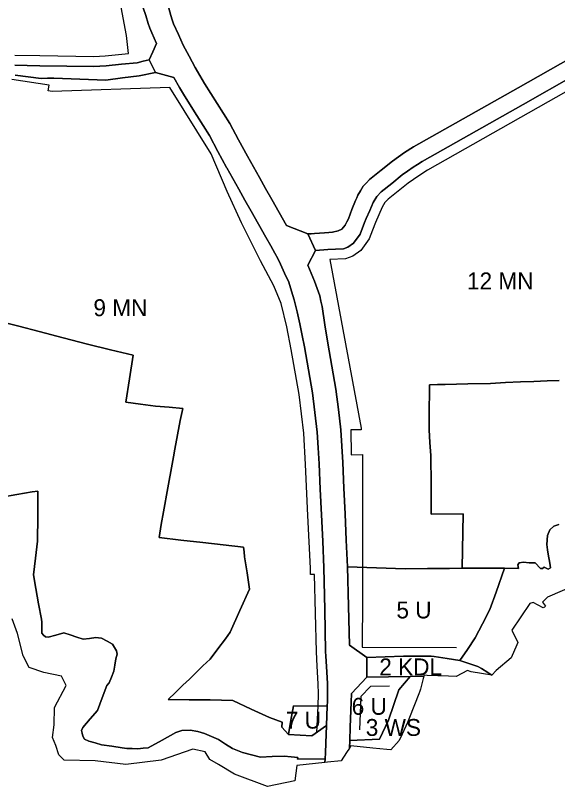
# Model space of a CAD drawing. Extents: x 7423432 to 7425824, y 5537848 to 5539677.
# Drawn here: x 7424289.1 to 7424610, y 5537848 to 5538304.6 of the extents above; entities that cross this region are included whole.
import ezdxf

# ---------------------------------------------------------------- set-up
doc = ezdxf.new("R2010")
doc.units = 0
for name, color, linetype in [('linie_rozgraniczajace', 7, 'Continuous'), ('linie_zabudowy_nieprzekraczalne', 7, 'Continuous'), ('oznaczenia_przeznaczen', 7, 'Continuous')]:
    doc.layers.add(name, color=color, linetype=linetype)

msp = doc.modelspace()

# ---------------------------------------------------------------- linework, layer by layer
at = {"layer": 'linie_rozgraniczajace'}
for points in [[(7424364.77, 5538309.08), (7424366.24, 5538304.49), (7424367.7, 5538299.89), (7424368.77, 5538297.09), (7424369.84, 5538294.29), (7424371.28, 5538291.11), (7424372.71, 5538287.94), (7424370.46, 5538283.14), (7424368.2, 5538278.34), (7424364.67, 5538277.48), (7424361.13, 5538276.62), (7424351.94, 5538275.67), (7424342.76, 5538274.72), (7424339.16, 5538274.52), (7424335.56, 5538274.33), (7424319.54, 5538274.56), (7424303.52, 5538274.8), (7424296.11, 5538274.99), (7424288.7, 5538275.17)], [(7424446.09, 5538157.4), (7424444.38, 5538160.62), (7424442.67, 5538163.84), (7424441.47, 5538166.01), (7424440.28, 5538168.18), (7424437.36, 5538173.35), (7424433, 5538181.05), (7424428.64, 5538188.75), (7424424.99, 5538195.23), (7424421.33, 5538201.71), (7424417.76, 5538208.04), (7424414.19, 5538214.37), (7424413.99, 5538214.5), (7424408.95, 5538224.05), (7424403.91, 5538233.61), (7424396.53, 5538245.3), (7424389.14, 5538257), (7424386.23, 5538262), (7424382.8, 5538267.96), (7424372.08, 5538270.76), (7424368.2, 5538278.34), (7424370.46, 5538283.14), (7424372.71, 5538287.94), (7424371.28, 5538291.11), (7424369.84, 5538294.29), (7424368.77, 5538297.09), (7424367.7, 5538299.89), (7424366.24, 5538304.49), (7424364.77, 5538309.08)], [(7424429.96, 5538214.91), (7424426.39, 5538221.24), (7424421.21, 5538230.93), (7424416.03, 5538240.62), (7424408.57, 5538252.44), (7424401.11, 5538264.26), (7424398.33, 5538269.04), (7424395.55, 5538273.82), (7424392, 5538280.45), (7424388.46, 5538287.09), (7424385.62, 5538293.38), (7424382.77, 5538299.67), (7424381.95, 5538302.08), (7424381.13, 5538304.5), (7424379.86, 5538308.99)], [(7424379.86, 5538308.99), (7424381.13, 5538304.5), (7424381.95, 5538302.08), (7424382.77, 5538299.67), (7424385.62, 5538293.38), (7424388.46, 5538287.09), (7424392, 5538280.45), (7424395.55, 5538273.82), (7424398.33, 5538269.04), (7424401.11, 5538264.26), (7424408.57, 5538252.44), (7424416.03, 5538240.62), (7424421.21, 5538230.93), (7424426.39, 5538221.24), (7424429.96, 5538214.91), (7424433.52, 5538208.59), (7424437.18, 5538202.11), (7424440.83, 5538195.64), (7424445.17, 5538187.97), (7424449.5, 5538180.31), (7424462.18, 5538175.24), (7424466.64, 5538165.51), (7424462.17, 5538156.69), (7424464.16, 5538151.96), (7424466.15, 5538147.23), (7424467.74, 5538142.96), (7424469.34, 5538138.68), (7424469.98, 5538135.45), (7424470.62, 5538132.22), (7424472.32, 5538121.43), (7424474.02, 5538110.65), (7424476.39, 5538096.98), (7424478.76, 5538083.32), (7424480.26, 5538071.27), (7424481.76, 5538059.21), (7424482.32, 5538049.57), (7424482.87, 5538039.92), (7424483.56, 5538024.76), (7424484.24, 5538009.59), (7424484.97, 5537993.86), (7424485.7, 5537978.12), (7424486.31, 5537954.94), (7424486.92, 5537931.75), (7424497.08, 5537924.38), (7424497.11, 5537912.86), (7424488.06, 5537903.12), (7424487.86, 5537898.1), (7424487.67, 5537893.08), (7424487.29, 5537883.18), (7424486.98, 5537875.31), (7424486.86, 5537870.87), (7424485.04, 5537868.13), (7424481.86, 5537863.34), (7424473.91, 5537862.5), (7424472.28, 5537862.33), (7424472.4, 5537864.54), (7424472.6, 5537868.02), (7424472.91, 5537873.7), (7424473.31, 5537884.12), (7424473.72, 5537895.66), (7424473.78, 5537898.35), (7424473.87, 5537903.07), (7424473.83, 5537906.11), (7424473.78, 5537909.14), (7424473.39, 5537915.75), (7424473, 5537922.36), (7424472.83, 5537925.23), (7424472.66, 5537928.1), (7424472.19, 5537952.86), (7424471.71, 5537977.61), (7424470.99, 5537993.28), (7424470.26, 5538008.95), (7424469.57, 5538024.08), (7424468.89, 5538039.2), (7424468.35, 5538048.57), (7424467.81, 5538057.94), (7424466.36, 5538069.6), (7424464.91, 5538081.26), (7424462.56, 5538094.81), (7424460.21, 5538108.36), (7424458.87, 5538115.15), (7424457.53, 5538121.93), (7424455.82, 5538129.08), (7424454.11, 5538136.22), (7424452.48, 5538141.45), (7424450.85, 5538146.69), (7424448.47, 5538152.04), (7424446.09, 5538157.4)], [(7424648.72, 5538296.91), (7424586.75, 5538261.84), (7424524.77, 5538226.77), (7424519.38, 5538223.37), (7424512.31, 5538218.35), (7424505.54, 5538212.92), (7424498.78, 5538207.49), (7424496.89, 5538205.46), (7424495.01, 5538203.43), (7424493.44, 5538200.82), (7424491.86, 5538198.2), (7424491.14, 5538196.63), (7424490.41, 5538195.05), (7424488.31, 5538189.65), (7424486.21, 5538184.24), (7424485.25, 5538182.34), (7424484.29, 5538180.43), (7424482.41, 5538177.97), (7424480.24, 5538176.99), (7424476.88, 5538176.25), (7424474.6, 5538176.07), (7424472.11, 5538175.87), (7424469.16, 5538175.7), (7424466.22, 5538175.53), (7424464.2, 5538175.39), (7424462.18, 5538175.24), (7424449.5, 5538180.31), (7424445.17, 5538187.97), (7424440.83, 5538195.64), (7424437.18, 5538202.11), (7424433.52, 5538208.59), (7424429.96, 5538214.91)], [(7424462.18, 5538175.24), (7424464.2, 5538175.39), (7424466.22, 5538175.53), (7424469.16, 5538175.7), (7424472.11, 5538175.87), (7424474.6, 5538176.07), (7424476.88, 5538176.25), (7424480.24, 5538176.99), (7424482.41, 5538177.97), (7424484.29, 5538180.43), (7424485.25, 5538182.34), (7424486.21, 5538184.24), (7424488.31, 5538189.65), (7424490.41, 5538195.05), (7424491.14, 5538196.63), (7424491.86, 5538198.2), (7424493.44, 5538200.82), (7424495.01, 5538203.43), (7424496.89, 5538205.46), (7424498.78, 5538207.49), (7424505.54, 5538212.92), (7424512.31, 5538218.35), (7424519.38, 5538223.37), (7424524.77, 5538226.77), (7424586.75, 5538261.84), (7424648.72, 5538296.91)], [(7424610.91, 5538088.47), (7424603.87, 5538088.22), (7424595.97, 5538087.93), (7424588.08, 5538087.65), (7424579.16, 5538087.21), (7424570.25, 5538086.76), (7424556.9, 5538086.45), (7424543.55, 5538086.13), (7424538.86, 5538086.02), (7424534.17, 5538085.91), (7424534.14, 5538082.08), (7424534.04, 5538070.65), (7424533.95, 5538059.21), (7424534.46, 5538051.68), (7424534.97, 5538044.15), (7424535.12, 5538026.7), (7424535.28, 5538009.25), (7424554.19, 5538009.46), (7424553.63, 5537977.3), (7424546.07, 5537977.24), (7424532.96, 5537977.14), (7424519.85, 5537977.03), (7424502.78, 5537977.58), (7424485.7, 5537978.12), (7424484.97, 5537993.86), (7424484.24, 5538009.59), (7424483.56, 5538024.76), (7424482.87, 5538039.92), (7424482.32, 5538049.57), (7424481.76, 5538059.21), (7424480.26, 5538071.27), (7424478.76, 5538083.32), (7424476.39, 5538096.98), (7424474.02, 5538110.65), (7424472.32, 5538121.43), (7424470.62, 5538132.22), (7424469.98, 5538135.45), (7424469.34, 5538138.68), (7424467.74, 5538142.96), (7424466.15, 5538147.23), (7424464.16, 5538151.96), (7424462.17, 5538156.69), (7424466.64, 5538165.51), (7424473.97, 5538166.02), (7424478.66, 5538166.22), (7424483.34, 5538166.42), (7424485.94, 5538167.34), (7424489.17, 5538169.73), (7424493.13, 5538175.17), (7424495.77, 5538182), (7424496.71, 5538184.38), (7424498.8, 5538189.1), (7424500.9, 5538193.82), (7424503.04, 5538197.39), (7424505.68, 5538200.22), (7424511.86, 5538205.2), (7424518.04, 5538210.18), (7424521.26, 5538212.43), (7424524.48, 5538214.68), (7424527.15, 5538216.41), (7424529.82, 5538218.13), (7424589.55, 5538251.94), (7424649.28, 5538285.74)], [(7424649.28, 5538285.74), (7424589.55, 5538251.94), (7424529.82, 5538218.13), (7424527.15, 5538216.41), (7424524.48, 5538214.68), (7424521.26, 5538212.43), (7424518.04, 5538210.18), (7424511.86, 5538205.2), (7424505.68, 5538200.22), (7424503.04, 5538197.39), (7424500.9, 5538193.82), (7424498.8, 5538189.1), (7424496.71, 5538184.38), (7424495.77, 5538182), (7424493.13, 5538175.17), (7424489.17, 5538169.73), (7424485.94, 5538167.34), (7424483.34, 5538166.42), (7424478.66, 5538166.22), (7424473.97, 5538166.02), (7424466.64, 5538165.51), (7424462.18, 5538175.24)], [(7424288.7, 5538275.17), (7424296.11, 5538274.99), (7424303.52, 5538274.8), (7424319.54, 5538274.56), (7424335.56, 5538274.33), (7424339.16, 5538274.52), (7424342.76, 5538274.72), (7424351.94, 5538275.67), (7424361.13, 5538276.62), (7424364.67, 5538277.48), (7424368.2, 5538278.34), (7424372.08, 5538270.76), (7424362.33, 5538268.82), (7424352.48, 5538267.59), (7424342.63, 5538266.37), (7424327.25, 5538266.91), (7424311.88, 5538267.45), (7424308.1, 5538267.39), (7424304.32, 5538267.33), (7424296.63, 5538268.28), (7424288.93, 5538269.22)], [(7424288.93, 5538269.22), (7424296.63, 5538268.28), (7424304.32, 5538267.33), (7424308.1, 5538267.39), (7424311.88, 5538267.45), (7424327.25, 5538266.91), (7424342.63, 5538266.37), (7424352.48, 5538267.59), (7424362.33, 5538268.82), (7424372.08, 5538270.76), (7424382.8, 5538267.96), (7424386.23, 5538262), (7424389.14, 5538257), (7424396.53, 5538245.3), (7424403.91, 5538233.61), (7424408.95, 5538224.05), (7424413.99, 5538214.5), (7424414.19, 5538214.37), (7424417.76, 5538208.04), (7424421.33, 5538201.71), (7424424.99, 5538195.23), (7424428.64, 5538188.75), (7424433, 5538181.05), (7424437.36, 5538173.35), (7424440.28, 5538168.18), (7424441.47, 5538166.01), (7424442.67, 5538163.84), (7424444.38, 5538160.62), (7424446.09, 5538157.4), (7424448.47, 5538152.04), (7424450.85, 5538146.69), (7424452.48, 5538141.45), (7424454.11, 5538136.22), (7424455.82, 5538129.08), (7424457.53, 5538121.93), (7424458.87, 5538115.15), (7424460.21, 5538108.36), (7424462.56, 5538094.81), (7424464.91, 5538081.26), (7424466.36, 5538069.6), (7424467.81, 5538057.94), (7424468.35, 5538048.57), (7424468.89, 5538039.2), (7424469.57, 5538024.08), (7424470.26, 5538008.95), (7424470.99, 5537993.28), (7424471.71, 5537977.61), (7424472.19, 5537952.86), (7424472.66, 5537928.1), (7424472.83, 5537925.23), (7424473, 5537922.36), (7424473.39, 5537915.75), (7424473.78, 5537909.14), (7424473.83, 5537906.11), (7424473.87, 5537903.07), (7424473.78, 5537898.35), (7424473.72, 5537895.66), (7424453.63, 5537895.93), (7424452.16, 5537887.35), (7424450.68, 5537878.78), (7424446.74, 5537883.22), (7424447.09, 5537886.1), (7424439.49, 5537888.94), (7424428.6, 5537893.95), (7424417.71, 5537898.96), (7424404.44, 5537899.36), (7424391.94, 5537899.44), (7424379.44, 5537899.53), (7424383.87, 5537903.8), (7424388.3, 5537908.07), (7424392.09, 5537911.72), (7424395.88, 5537915.38), (7424400.12, 5537919.47), (7424404.37, 5537923.56), (7424408.88, 5537929.55), (7424413.4, 5537935.55)], [(7424413.4, 5537935.55), (7424414.8, 5537937.55), (7424416.21, 5537939.56), (7424421.95, 5537952.21), (7424427.7, 5537964.87), (7424426.24, 5537974.51), (7424424.79, 5537984.15), (7424424.43, 5537987.01), (7424424.08, 5537989.86), (7424412.07, 5537991.21), (7424400.06, 5537992.57), (7424387.1, 5537994.02), (7424374.14, 5537995.48), (7424375.45, 5538003.11), (7424376.76, 5538010.75), (7424379.29, 5538024.82), (7424381.82, 5538038.89), (7424382.61, 5538043.32), (7424383.41, 5538047.75), (7424385.06, 5538056.24), (7424386.71, 5538064.73), (7424388.21, 5538071.96), (7424380.1, 5538072.63), (7424371.98, 5538073.31), (7424363.19, 5538074.46), (7424354.4, 5538075.61), (7424356.62, 5538089.51), (7424358.85, 5538103.42), (7424345.3, 5538106.71), (7424331.74, 5538110), (7424317.47, 5538113.76), (7424303.2, 5538117.52), (7424291.16, 5538120.58), (7424279.12, 5538123.64)], [(7424279.12, 5538123.64), (7424291.16, 5538120.58), (7424303.2, 5538117.52), (7424317.47, 5538113.76), (7424331.74, 5538110), (7424345.3, 5538106.71), (7424358.85, 5538103.42), (7424356.62, 5538089.51), (7424354.4, 5538075.61), (7424363.19, 5538074.46), (7424371.98, 5538073.31), (7424380.1, 5538072.63), (7424388.21, 5538071.96), (7424386.71, 5538064.73), (7424385.06, 5538056.24), (7424383.41, 5538047.75), (7424382.61, 5538043.32), (7424381.82, 5538038.89), (7424379.29, 5538024.82), (7424376.76, 5538010.75), (7424375.45, 5538003.11), (7424374.14, 5537995.48), (7424387.1, 5537994.02), (7424400.06, 5537992.57), (7424412.07, 5537991.21), (7424424.08, 5537989.86), (7424424.43, 5537987.01), (7424424.79, 5537984.15), (7424426.24, 5537974.51), (7424427.7, 5537964.87), (7424421.95, 5537952.21), (7424416.21, 5537939.56), (7424414.8, 5537937.55), (7424413.4, 5537935.55), (7424408.88, 5537929.55), (7424404.37, 5537923.56), (7424400.12, 5537919.47), (7424395.88, 5537915.38), (7424392.09, 5537911.72), (7424388.3, 5537908.07), (7424383.87, 5537903.8), (7424379.44, 5537899.53), (7424391.94, 5537899.44), (7424404.44, 5537899.36), (7424417.71, 5537898.96), (7424428.6, 5537893.95), (7424439.49, 5537888.94), (7424447.09, 5537886.1), (7424446.74, 5537883.22), (7424450.68, 5537878.78), (7424464.63, 5537878.02), (7424473.31, 5537884.12), (7424472.91, 5537873.7), (7424472.6, 5537868.02), (7424472.4, 5537864.54), (7424455.98, 5537864.23), (7424456.36, 5537865.35), (7424452.25, 5537865.7), (7424448.13, 5537866.05), (7424441.17, 5537865.78), (7424434.22, 5537865.5), (7424423.43, 5537868.18), (7424417.56, 5537870.55), (7424413.48, 5537873.19), (7424409.39, 5537875.84), (7424405.19, 5537877.62), (7424400.98, 5537879.41), (7424399.01, 5537880), (7424397.04, 5537880.6), (7424392.62, 5537881.39), (7424387.61, 5537881.22), (7424384.03, 5537879.99), (7424375.89, 5537875.52), (7424367.75, 5537871.05), (7424364.69, 5537870.73), (7424361.63, 5537870.41), (7424358.32, 5537870.51), (7424355.02, 5537870.62), (7424352.3, 5537870.96), (7424346.22, 5537871.87), (7424340.15, 5537872.78), (7424336.32, 5537873.85), (7424332.49, 5537874.92), (7424330.06, 5537876.12), (7424328.95, 5537877.95), (7424328.6, 5537879.63), (7424328.24, 5537881.31)], [(7424535.28, 5538009.25), (7424535.12, 5538026.7), (7424534.97, 5538044.15), (7424534.46, 5538051.68), (7424533.95, 5538059.21), (7424534.04, 5538070.65), (7424534.14, 5538082.08), (7424534.17, 5538085.91), (7424538.86, 5538086.02), (7424543.55, 5538086.13), (7424556.9, 5538086.45), (7424570.25, 5538086.76), (7424579.16, 5538087.21), (7424588.08, 5538087.65), (7424595.97, 5538087.93), (7424603.87, 5538088.22), (7424610.91, 5538088.47)], [(7424328.24, 5537881.31), (7424328.96, 5537882.99), (7424333.34, 5537888.08), (7424337.72, 5537893.17), (7424340.43, 5537900.54), (7424343.14, 5537907.91), (7424344.53, 5537909.52), (7424345.94, 5537912.91), (7424347.35, 5537916.3), (7424347.93, 5537920), (7424348.51, 5537923.7), (7424348.92, 5537925.1), (7424349.33, 5537926.5), (7424348.96, 5537928.49), (7424347.81, 5537930.47), (7424346.66, 5537932.44), (7424343.34, 5537934.18), (7424340.02, 5537935.92), (7424338.39, 5537936.13), (7424336.76, 5537936.35), (7424333.02, 5537935.8), (7424329.28, 5537935.25), (7424325.41, 5537936.58), (7424321.55, 5537937.91), (7424317.77, 5537939.02), (7424313.13, 5537937.73), (7424308.49, 5537936.44), (7424306.9, 5537936.63), (7424305.79, 5537937.77), (7424304.68, 5537938.91), (7424304.76, 5537941.33), (7424304.84, 5537943.75), (7424304.67, 5537945.46), (7424304.5, 5537947.17), (7424302.88, 5537956.26), (7424301.27, 5537965.35), (7424299.85, 5537973.31), (7424301.06, 5537983.34), (7424302.27, 5537993.37), (7424302.32, 5538008.12), (7424302.36, 5538022.88), (7424298.94, 5538022.63), (7424290.01, 5538021.01), (7424281.07, 5538019.4)], [(7424281.07, 5538019.4), (7424290.01, 5538021.01), (7424298.94, 5538022.63), (7424302.36, 5538022.88), (7424302.32, 5538008.12), (7424302.27, 5537993.37), (7424301.06, 5537983.34), (7424299.85, 5537973.31), (7424301.27, 5537965.35), (7424302.88, 5537956.26), (7424304.5, 5537947.17), (7424304.67, 5537945.46), (7424304.84, 5537943.75), (7424304.76, 5537941.33), (7424304.68, 5537938.91), (7424305.79, 5537937.77), (7424306.9, 5537936.63), (7424308.49, 5537936.44), (7424313.13, 5537937.73), (7424317.77, 5537939.02), (7424321.55, 5537937.91), (7424325.41, 5537936.58), (7424329.28, 5537935.25), (7424333.02, 5537935.8), (7424336.76, 5537936.35), (7424338.39, 5537936.13), (7424340.02, 5537935.92), (7424343.34, 5537934.18), (7424346.66, 5537932.44), (7424347.81, 5537930.47), (7424348.96, 5537928.49), (7424349.33, 5537926.5), (7424348.92, 5537925.1), (7424348.51, 5537923.7), (7424347.93, 5537920), (7424347.35, 5537916.3), (7424345.94, 5537912.91), (7424344.53, 5537909.52), (7424343.14, 5537907.91), (7424340.43, 5537900.54), (7424337.72, 5537893.17), (7424333.34, 5537888.08), (7424328.96, 5537882.99), (7424328.24, 5537881.31), (7424328.6, 5537879.63), (7424328.95, 5537877.95), (7424330.06, 5537876.12), (7424332.49, 5537874.92), (7424336.32, 5537873.85), (7424340.15, 5537872.78), (7424346.22, 5537871.87), (7424352.3, 5537870.96), (7424355.02, 5537870.62), (7424358.32, 5537870.51), (7424361.63, 5537870.41)], [(7424610.78, 5538003.24), (7424607.73, 5538002.23), (7424605.39, 5538000.01), (7424604.13, 5537996.65), (7424603.62, 5537991.3), (7424604, 5537988.19), (7424604.44, 5537985.67), (7424605.34, 5537980.36), (7424605.77, 5537977.48), (7424604.51, 5537976.86), (7424602.12, 5537977.91), (7424601.03, 5537977.19), (7424599.88, 5537977.06), (7424596.64, 5537980.61), (7424593.11, 5537980.49), (7424589.76, 5537980.97), (7424587.32, 5537980.5), (7424586.44, 5537979.23), (7424586.96, 5537977.19), (7424578.57, 5537977.29), (7424573.86, 5537977.29), (7424569.14, 5537977.29), (7424561.39, 5537977.3), (7424553.63, 5537977.3), (7424554.19, 5538009.46), (7424535.28, 5538009.25)], [(7424552.24, 5537922.69), (7424556.64, 5537929.24), (7424561.24, 5537936.09), (7424565.62, 5537944.49), (7424569.99, 5537952.88), (7424573.58, 5537963.09), (7424578.57, 5537977.29), (7424586.96, 5537977.19), (7424586.44, 5537979.23), (7424587.32, 5537980.5), (7424589.76, 5537980.97), (7424593.11, 5537980.49), (7424596.64, 5537980.61), (7424599.88, 5537977.06), (7424601.03, 5537977.19), (7424602.12, 5537977.91), (7424604.51, 5537976.86), (7424605.77, 5537977.48), (7424605.34, 5537980.36), (7424604.44, 5537985.67), (7424604, 5537988.19), (7424603.62, 5537991.3), (7424604.13, 5537996.65), (7424605.39, 5538000.01), (7424607.73, 5538002.23), (7424610.78, 5538003.24)], [(7424621.48, 5537967.64), (7424603.96, 5537960.23), (7424601.06, 5537957.18), (7424602.79, 5537954.87), (7424602.36, 5537954.26), (7424601.54, 5537953.87), (7424595.5, 5537956.94), (7424593.49, 5537956.46), (7424582.94, 5537940.67), (7424586.51, 5537933.33), (7424585.9, 5537931.98), (7424582.46, 5537924.27), (7424573.57, 5537916.8), (7424571.07, 5537914.07), (7424568.74, 5537915.51), (7424564.9, 5537917.86), (7424562.77, 5537919.18), (7424557.51, 5537920.93), (7424552.24, 5537922.69)], [(7424361.63, 5537870.41), (7424364.69, 5537870.73), (7424367.75, 5537871.05), (7424375.89, 5537875.52), (7424384.03, 5537879.99), (7424387.61, 5537881.22), (7424392.62, 5537881.39), (7424397.04, 5537880.6), (7424399.01, 5537880), (7424400.98, 5537879.41), (7424405.19, 5537877.62), (7424409.39, 5537875.84), (7424413.48, 5537873.19), (7424417.56, 5537870.55), (7424423.43, 5537868.18), (7424434.22, 5537865.5), (7424441.17, 5537865.78), (7424448.13, 5537866.05), (7424452.25, 5537865.7), (7424456.36, 5537865.35), (7424455.98, 5537864.23), (7424472.4, 5537864.54), (7424472.28, 5537862.33), (7424455.59, 5537860.58), (7424454.59, 5537851.4), (7424438.3, 5537848.04), (7424418.69, 5537855.42), (7424409.27, 5537861.07), (7424404.18, 5537863.99), (7424401.49, 5537868.53), (7424394.2, 5537870.14), (7424375.35, 5537863.65), (7424354.39, 5537861.15), (7424336.3, 5537863.2), (7424317.99, 5537863.65), (7424314.86, 5537866.9), (7424313.12, 5537872.31), (7424311.13, 5537877.16), (7424311.98, 5537884.52), (7424312.23, 5537894.81), (7424319.2, 5537907.92), (7424316.43, 5537913.46), (7424305.85, 5537915.5), (7424297.2, 5537918.48), (7424293.71, 5537925.38), (7424290.35, 5537938.66), (7424287.2, 5537947.38)]]:
    msp.add_lwpolyline(points, dxfattribs=at)
for points in [[(7424486.92, 5537931.75), (7424486.31, 5537954.94), (7424485.7, 5537978.12), (7424502.78, 5537977.58), (7424519.85, 5537977.03), (7424532.96, 5537977.14), (7424546.07, 5537977.24), (7424553.63, 5537977.3), (7424561.39, 5537977.3), (7424569.14, 5537977.29), (7424573.86, 5537977.29), (7424578.57, 5537977.29), (7424573.58, 5537963.09), (7424569.99, 5537952.88), (7424565.62, 5537944.49), (7424561.24, 5537936.09), (7424556.64, 5537929.24), (7424552.24, 5537922.69), (7424544.6, 5537923.88), (7424536.96, 5537925.08), (7424535.11, 5537925.21), (7424533.26, 5537925.35), (7424526.02, 5537925.27), (7424518.77, 5537925.19), (7424507.93, 5537924.79), (7424497.08, 5537924.38)], [(7424497.11, 5537912.86), (7424497.08, 5537924.38), (7424507.93, 5537924.79), (7424518.77, 5537925.19), (7424526.02, 5537925.27), (7424533.26, 5537925.35), (7424535.11, 5537925.21), (7424536.96, 5537925.08), (7424544.6, 5537923.88), (7424552.24, 5537922.69), (7424557.51, 5537920.93), (7424562.77, 5537919.18), (7424564.9, 5537917.86), (7424568.74, 5537915.51), (7424571.07, 5537914.07), (7424558.85, 5537915.91), (7424556.6, 5537916.8), (7424550.01, 5537913.26), (7424545.41, 5537913.32), (7424532.79, 5537913.9), (7424530.96, 5537913.95), (7424530.8, 5537913.32), (7424522.69, 5537913.23), (7424509.9, 5537913.04)], [(7424486.86, 5537870.87), (7424486.98, 5537875.31), (7424504.51, 5537876.2), (7424510.01, 5537887.31), (7424516.14, 5537905.31), (7424522.69, 5537913.23), (7424530.8, 5537913.32), (7424530.49, 5537912.08), (7424528.84, 5537905.67), (7424528.42, 5537904.57), (7424527.8, 5537902.91), (7424522.42, 5537888.85), (7424521.09, 5537885.88), (7424518.02, 5537879.04), (7424516.33, 5537875.27), (7424511.28, 5537869.8), (7424508.98, 5537870.03), (7424500.64, 5537870.86), (7424487.71, 5537872.16)], [(7424486.98, 5537875.31), (7424487.29, 5537883.18), (7424487.67, 5537893.08), (7424487.86, 5537898.1), (7424488.06, 5537903.12), (7424497.11, 5537912.86), (7424509.9, 5537913.04), (7424522.69, 5537913.23), (7424516.14, 5537905.31), (7424510.01, 5537887.31), (7424504.51, 5537876.2)], [(7424450.68, 5537878.78), (7424452.16, 5537887.35), (7424453.63, 5537895.93), (7424473.72, 5537895.66), (7424473.31, 5537884.12), (7424464.63, 5537878.02)]]:
    msp.add_lwpolyline(points, close=True, dxfattribs=at)
at = {"layer": 'linie_zabudowy_nieprzekraczalne'}
for points in [[(7424288.71, 5538281.18), (7424303.64, 5538280.8), (7424335.44, 5538280.33), (7424342.29, 5538280.7), (7424356.12, 5538282.13), (7424356.12, 5538282.13), (7424354.81, 5538292.7), (7424351.17, 5538312.61)], [(7424647.55, 5538277.87), (7424532.93, 5538213), (7424527.83, 5538209.7), (7424521.65, 5538205.38), (7424509.78, 5538195.82), (7424507.86, 5538193.76), (7424506.23, 5538191.05), (7424502.24, 5538182.05), (7424500.42, 5538177.46), (7424498.46, 5538172.29), (7424493.48, 5538165.45), (7424488.78, 5538161.99), (7424484.5, 5538160.47), (7424475.26, 5538160.13), (7424475.26, 5538160.13), (7424475.26, 5538160.13), (7424475.26, 5538160.13), (7424493.71, 5538060.3), (7424493.71, 5538060.3), (7424493.71, 5538060.3), (7424493.71, 5538060.3), (7424493.76, 5538059.21), (7424487.55, 5538059.21), (7424487.89, 5538044.42), (7424494.57, 5538044.59), (7424494.57, 5538044.59), (7424494.46, 5537959.52), (7424494.46, 5537959.52), (7424494.35, 5537930.52), (7424550.24, 5537930.46)], [(7424467.59, 5537880.1), (7424468.23, 5537895.73), (7424468.46, 5537902.97), (7424468.33, 5537908.84), (7424467.77, 5537919.36), (7424467.27, 5537927.89), (7424466.2, 5537973.56), (7424463.79, 5537973.54), (7424463.71, 5537977.35), (7424462.27, 5538008.59), (7424460.9, 5538038.79), (7424459.84, 5538057.22), (7424456.99, 5538080.08), (7424452.35, 5538106.91), (7424449.71, 5538120.23), (7424446.4, 5538134.1), (7424442.03, 5538144.47), (7424434.18, 5538159.26), (7424423, 5538181.88), (7424414.45, 5538200.46), (7424414.45, 5538200.46), (7424414.45, 5538200.46), (7424404.88, 5538222.6), (7424404.88, 5538222.6), (7424380.6, 5538261.92), (7424380.6, 5538261.92), (7424310.94, 5538259.6), (7424308.59, 5538259.96), (7424309.1, 5538263.27), (7424286.91, 5538266.75)], [(7424510.57, 5537907.58), (7424499.29, 5537907.35), (7424493.51, 5537901.42), (7424492.76, 5537881.61)]]:
    msp.add_lwpolyline(points, dxfattribs=at)

# ---------------------------------------------------------------- texts
at = {"layer": 'oznaczenia_przeznaczen'}
for s, p in [('12 MN', (7424556.4, 5538142.42)), ('9 MN', (7424335.28, 5538126.57)), ('5 U', (7424514.62, 5537947.6)), ('2 KDL', (7424504.48, 5537913.9)), ('6 U', (7424488.14, 5537890.55)), ('7 U', (7424449.14, 5537882.36)), ('3 WS', (7424496.49, 5537878.05))]:
    msp.add_text(s, height=10, dxfattribs=at).set_placement(p)

doc.saveas('drawing.dxf')
